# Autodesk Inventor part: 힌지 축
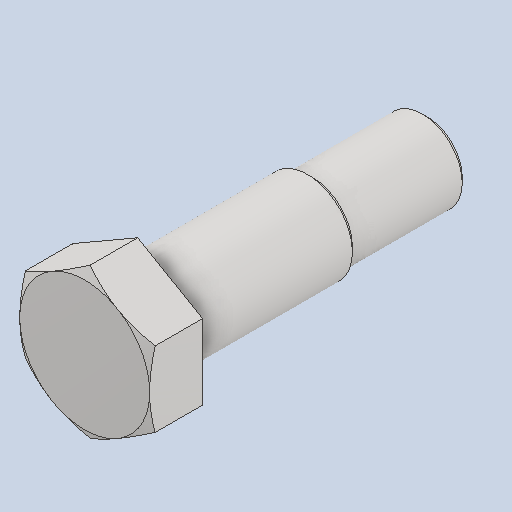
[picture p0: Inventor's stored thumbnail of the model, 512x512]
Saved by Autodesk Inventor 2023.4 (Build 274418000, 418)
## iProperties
Created: 2024-04
Part Number: 힌지 축
Material: 스테인리스강
Document SubType Name: Modeling
Designer: EDU
Density: 8.08 g/cm^3
Appearance: 기본값
Author: jhkim
Sending System: Autodesk Inventor 2025
Preprocessor: ST-DEVELOPER v20
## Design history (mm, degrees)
node "힌지 축1"
node "솔리드2"
node "솔리드1"
